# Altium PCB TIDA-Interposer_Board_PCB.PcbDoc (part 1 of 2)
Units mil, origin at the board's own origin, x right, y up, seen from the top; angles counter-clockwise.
Board outline 4000 x 3600 mil, 4 copper layers (Top Layer, GND, PWR, Bottom Layer), stack 5.48 mil thick; 55 components, 24 nets, 133 pads, 140 vias.
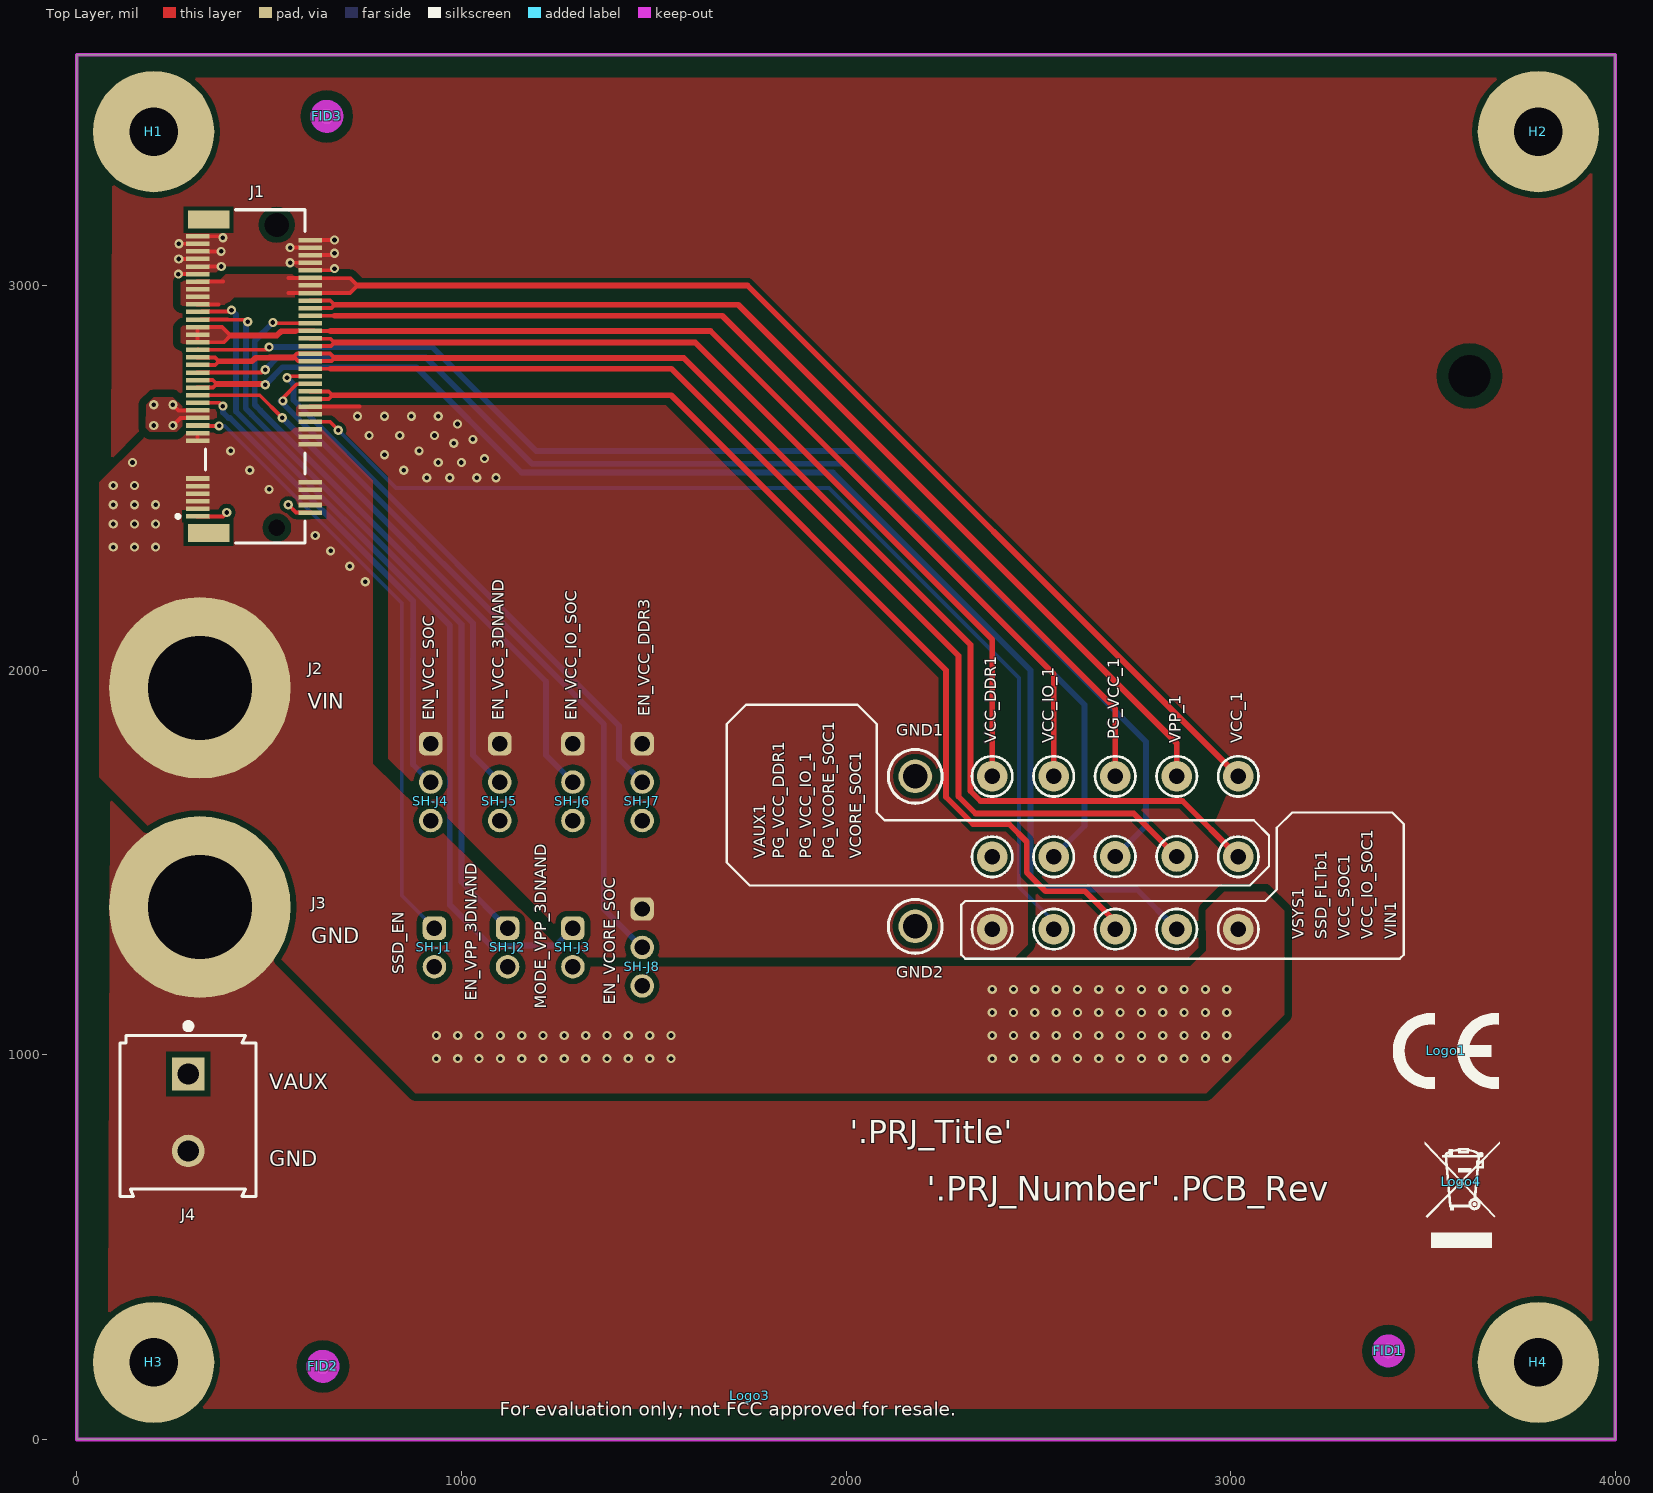
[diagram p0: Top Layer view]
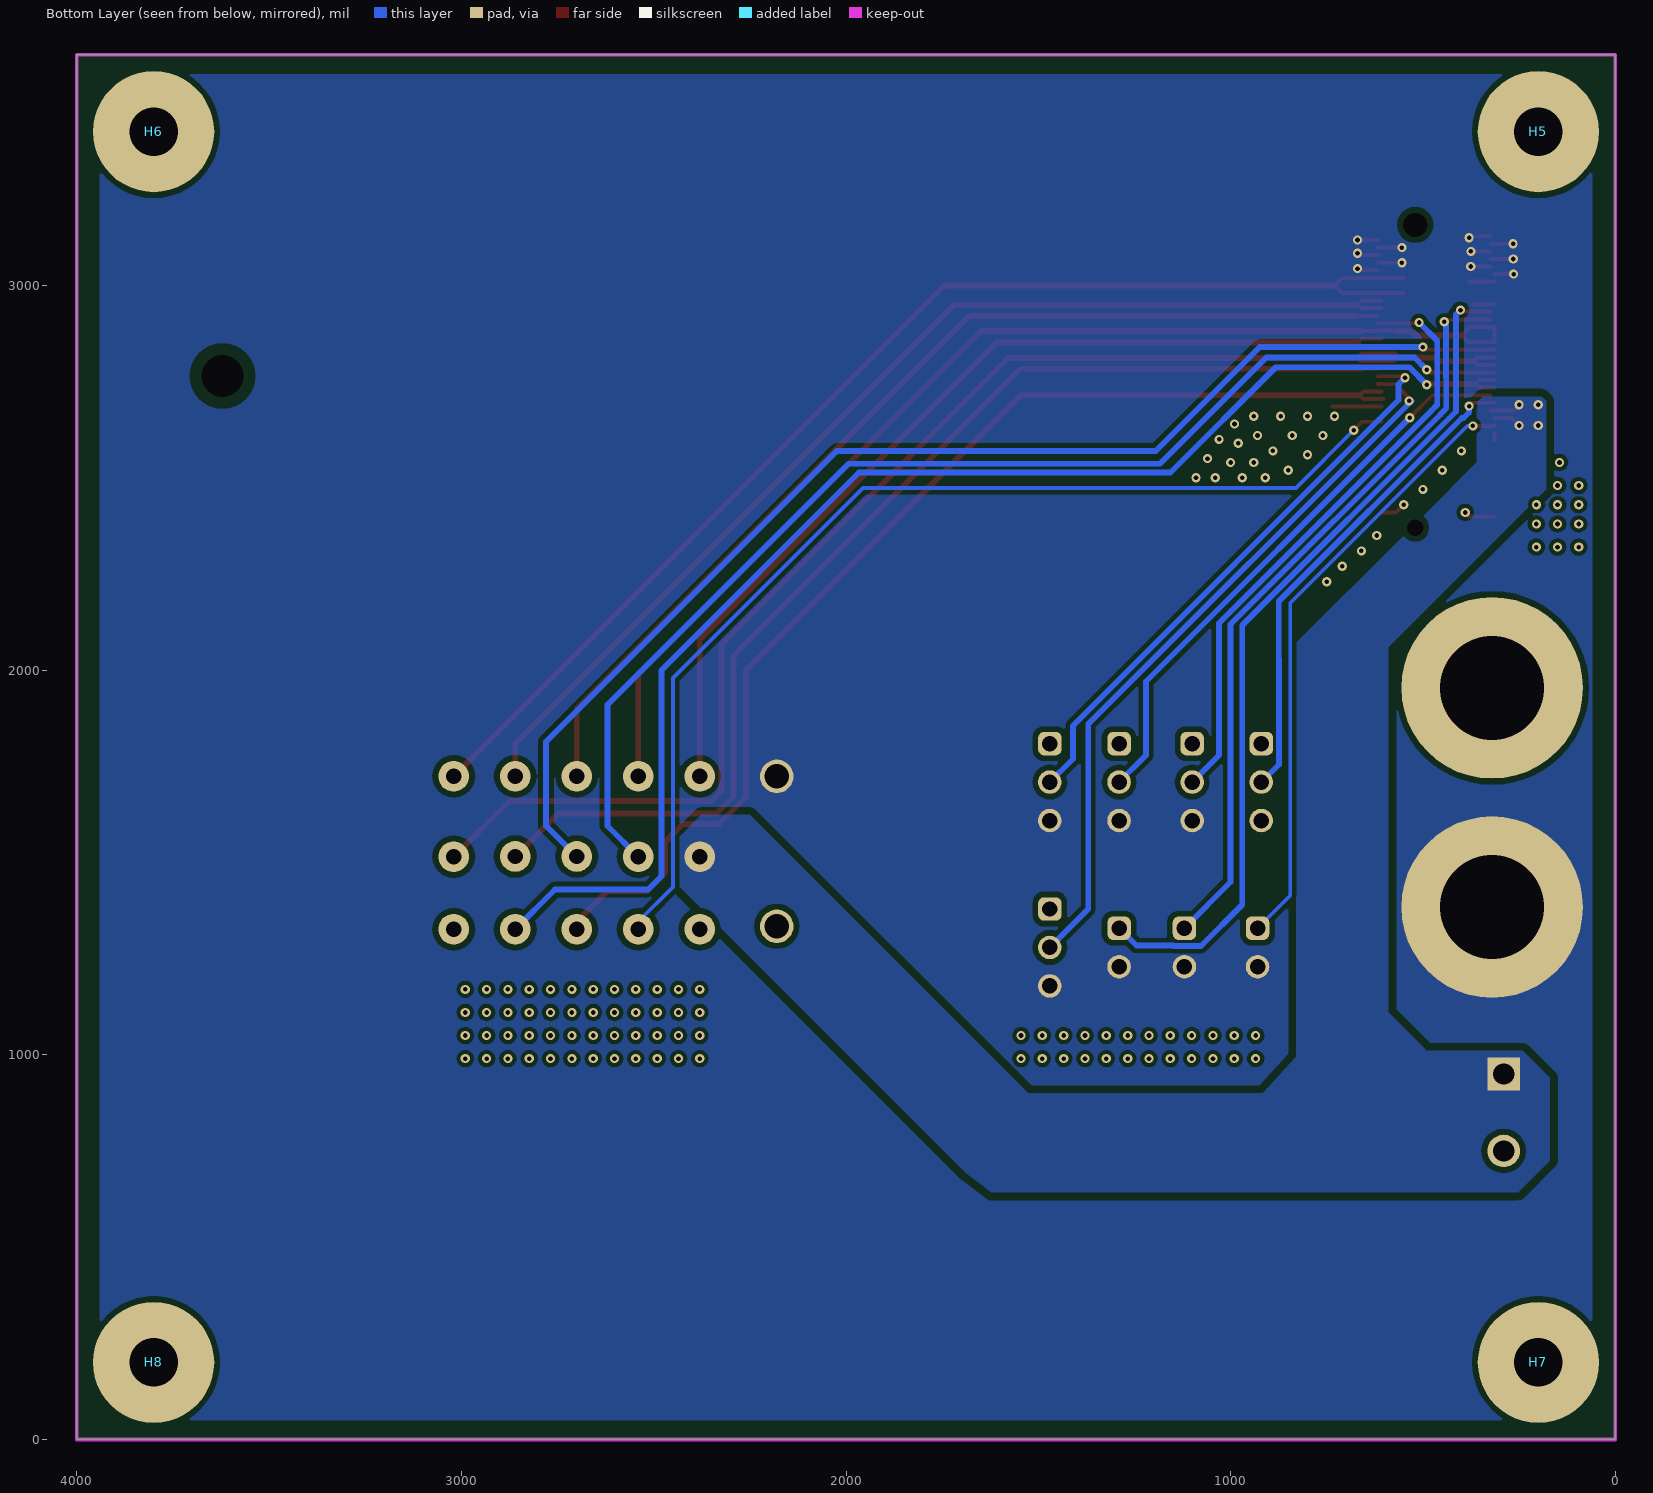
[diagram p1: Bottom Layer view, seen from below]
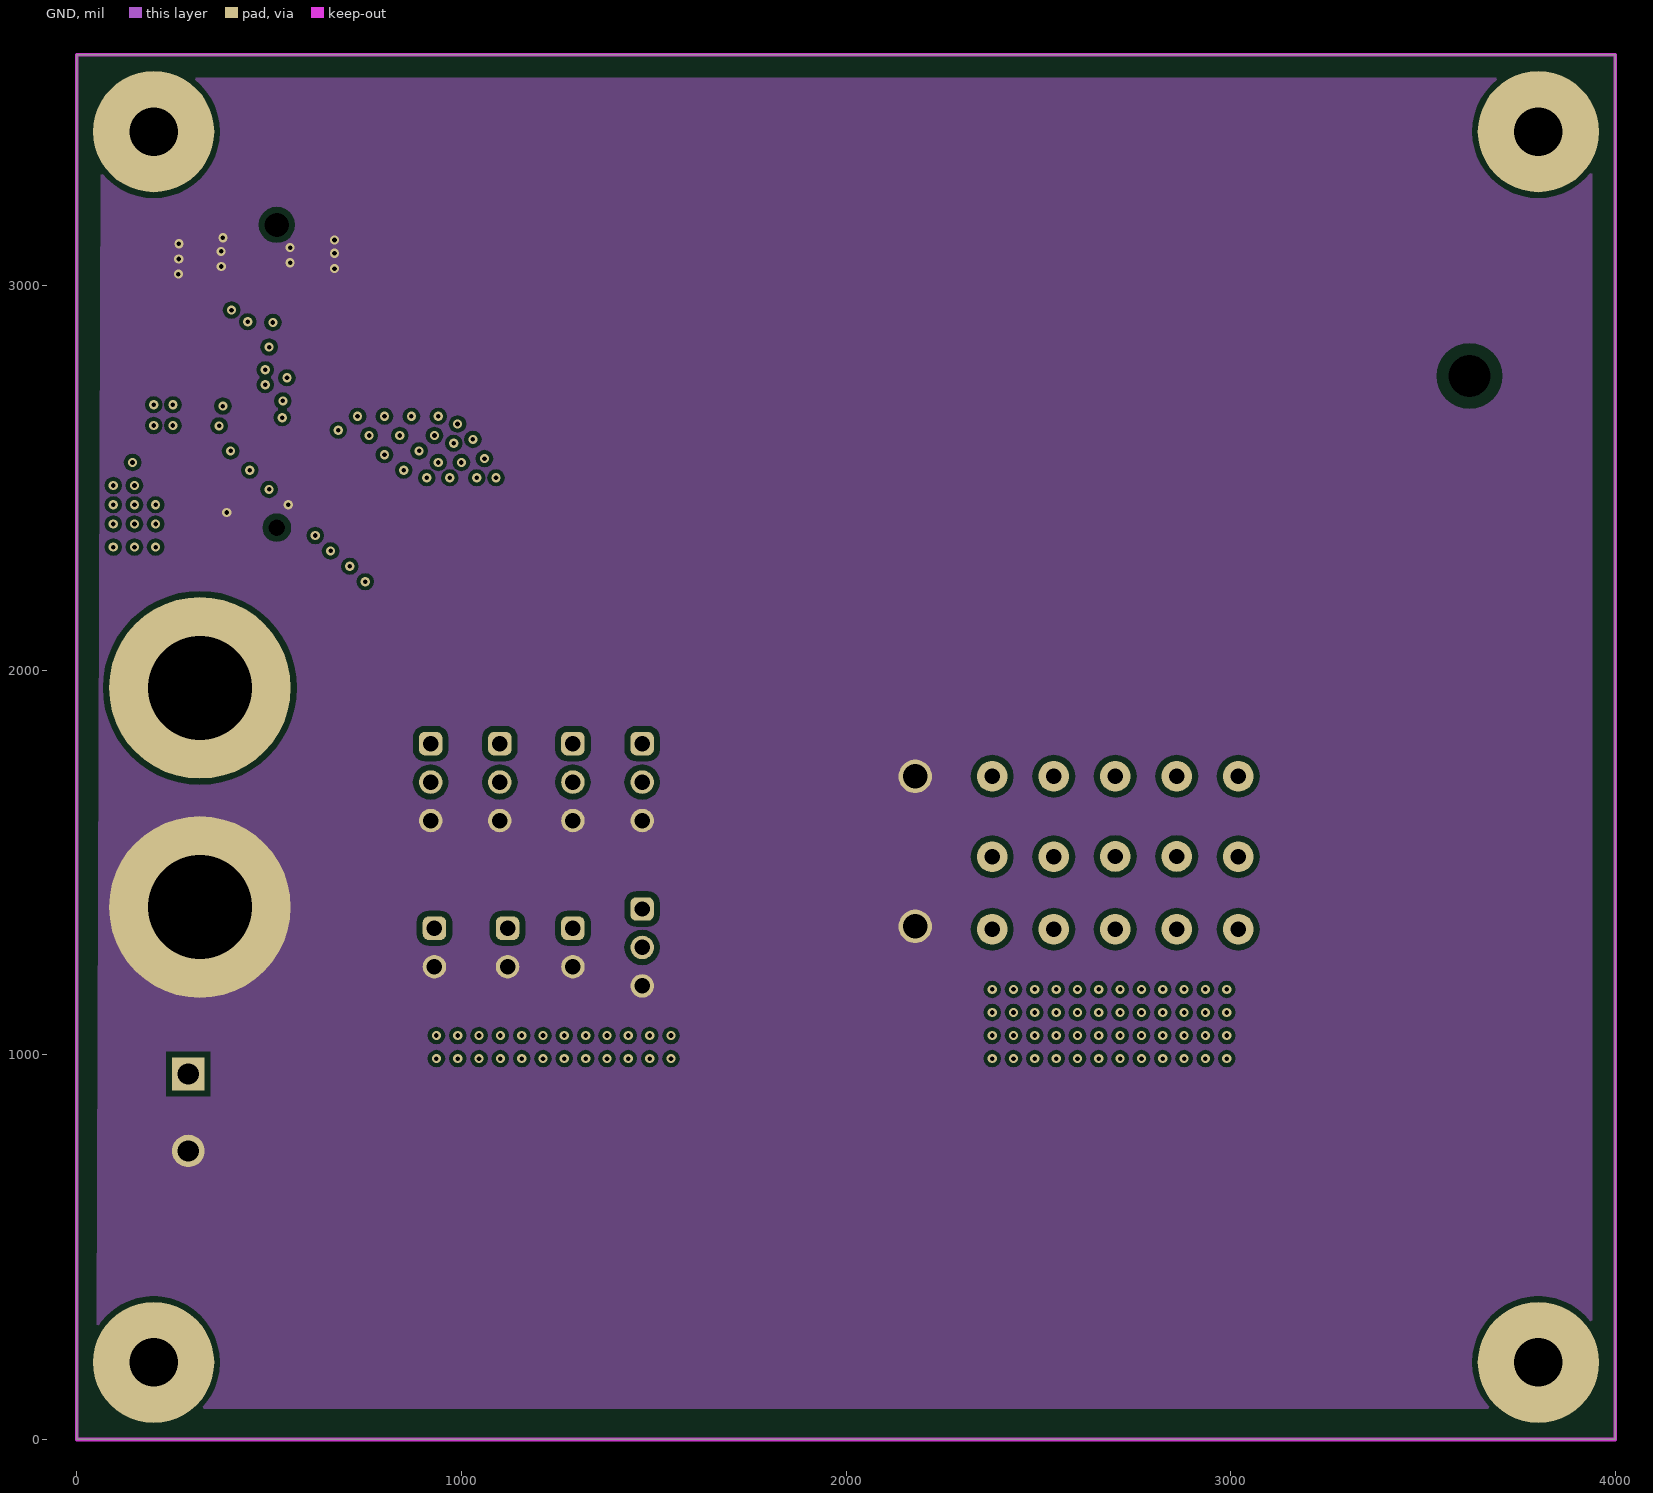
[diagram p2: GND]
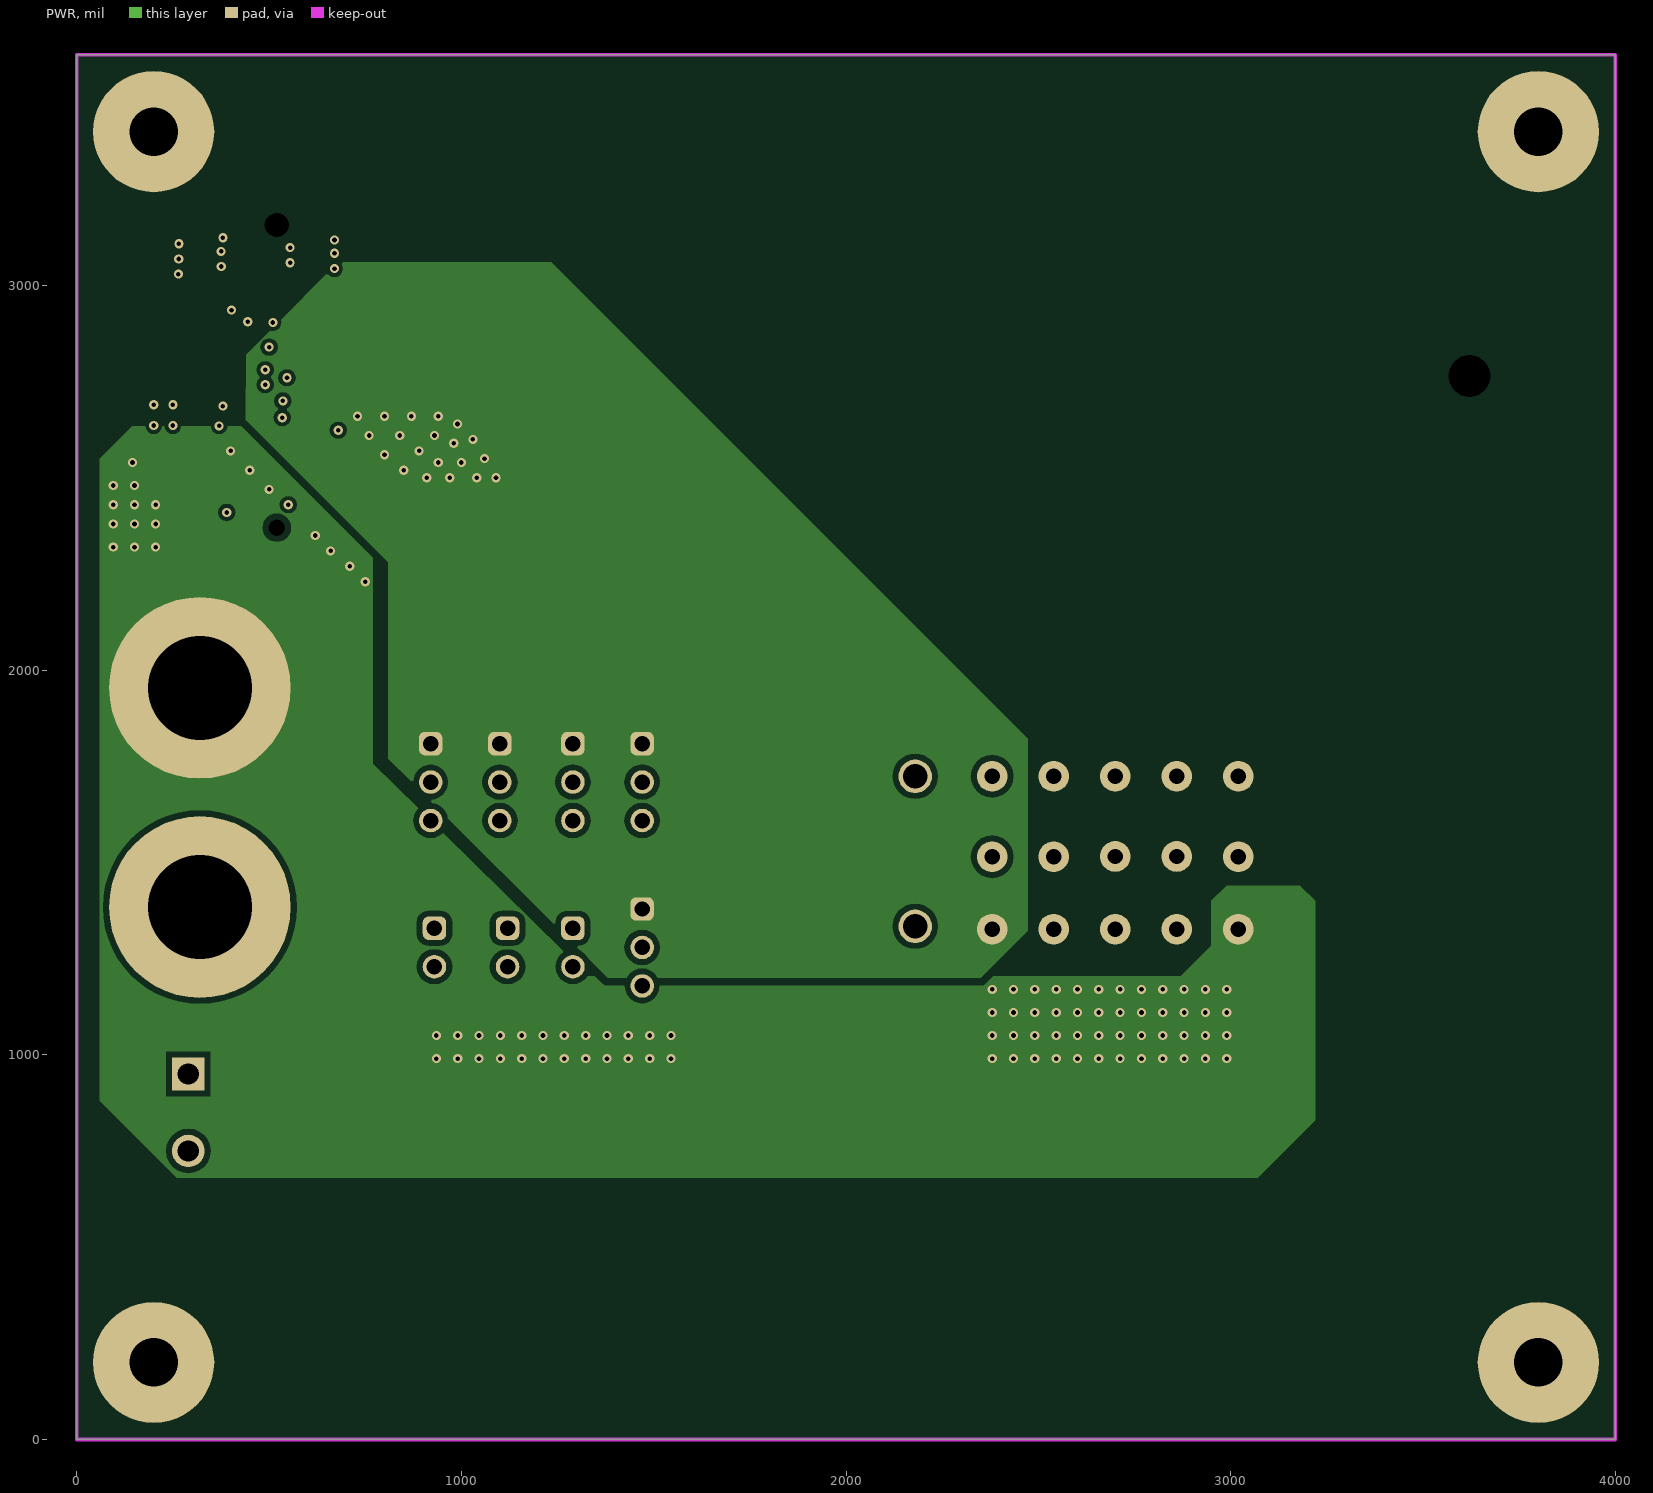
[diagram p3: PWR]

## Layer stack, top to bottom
Top Solder: solder mask 0.8, Solder Resist, Dk 0
Top Layer: signal copper 1.37
GND: signal copper 1.37
PWR: signal copper 1.37
Bottom Layer: signal copper 1.37
Bottom Solder: solder mask 0.8, Solder Resist, Dk 0

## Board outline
0,0 4000,0 4000,3600 0,3600

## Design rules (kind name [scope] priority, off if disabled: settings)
AcuteAngle [All] p1: minimum=4.50000000000000E+0001 checktracksonly=FALSE
AssemblyTestPointUsage [All] p1: valid=2
BoardOutlineClearance BoardOutlineClearance_MountingHoles [OnCopper and InComponentClass('Mounting Holes')] p1: gap=40 ignorepadtopadclearanceinfootprint=FALSE
BoardOutlineClearance BoardOutlineClearance_Poly [OnCopper and IsPoly] p2: gap=25 ignorepadtopadclearanceinfootprint=FALSE
BoardOutlineClearance [OnCopper and Not InComponentClass('Logo') and not InComponentClass('FiducialMark') and not InRegion(1000,500,4000,800) and not InPoly] p3: gap=75 ignorepadtopadclearanceinfootprint=FALSE
Clearance Clearance_MH100 [InPadClass('MH100')] p1: gap=30 ignorepadtopadclearanceinfootprint=FALSE
Clearance Clearance_Poly [InPolygon] p2: gap=25 ignorepadtopadclearanceinfootprint=FALSE except(0: Arc-Hole Track-Hole SMDPad-Hole THPad-Hole Via-Hole Fill-Hole Poly-Hole Region-Hole Text-Hole; 10: SMDPad-Poly Via-Poly; 12: Track-Poly; 15: THPad-Poly; 20: Poly-Poly)
Clearance Clearance_Keepouts [((IsTrack Or IsArc) And Not InPoly) And IsFree and IsKeepOut vs ((IsTrack Or IsArc) And Not InPoly) And IsFree and IsKeepOut] p3: gap=0 ignorepadtopadclearanceinfootprint=FALSE
Clearance [All] p4: gap=7.87 ignorepadtopadclearanceinfootprint=FALSE
Clearance Clearance_FiducialMark [IsKeepOut and InComponentClass('FID') vs IsPad and InComponentClass('FiducialMark')] p5: gap=0 ignorepadtopadclearanceinfootprint=FALSE
ComponentClearance ComponentClearance_MountingHoles_FiducialMarks [InComponentClass('Mounting Holes') vs InComponentClass('FiducialMark')] p1: gap=50 collisioncheckmode=3 verticalgap=10 showdistances=FALSE
ComponentClearance ComponentClearance_Shunt [InComponentClass('Header') vs InComponentClass('Shunt')] p2: gap=0 collisioncheckmode=3 verticalgap=0 showdistances=FALSE
ComponentClearance ComponentClearance_Logo [InComponentClass('Logo')] p3: gap=50 collisioncheckmode=3 verticalgap=10 showdistances=FALSE
ComponentClearance ComponentClearance_ScrewToNut [(HasFootprint('NY PMS 440 0025 PH')) vs (HasFootprint('Keystone_1902C'))] p4: gap=5 collisioncheckmode=3 verticalgap=10 showdistances=FALSE
ComponentClearance ComponentClearance_MountingHoles [InComponentClass('Mounting Holes')] p5: gap=100 collisioncheckmode=3 verticalgap=100000 showdistances=FALSE
ComponentClearance ComponentClearance_SmallPassives [HasFootprint('0201*') or HasFootprint('0402*') or HasFootprint('0508') or HasFootprint('0603*') or HasFootprint('0612') or HasFootprint('0805*') or HasFootprint('0815*') or HasFootprint('0830*') or HasFootprint('1206*') or HasFootprint('1210*') or HasFootprint('1808*') or HasFootprint('1812*') or HasFootprint('1825*') or HasFootprint('2010*') or HasFootprint('2220*') or HasFootprint('2225*') or HasFootprint('2512*') or HasFootprint('2728*') or HasFootprint('3518*') vs HasFootprint('0201*') or HasFootprint('0402*') or HasFootprint('0508') or HasFootprint('0603*') or HasFootprint('0612') or HasFootprint('0805*') or HasFootprint('0815*') or HasFootprint('0830*') or HasFootprint('1206*') or HasFootprint('1210*') or HasFootprint('1808*') or HasFootprint('1812*') or HasFootprint('1825*') or HasFootprint('2010*') or HasFootprint('2220*') or HasFootprint('2225*') or HasFootprint('2512*') or HasFootprint('2728*') or HasFootprint('3518*')] p6: gap=14.96 collisioncheckmode=3 verticalgap=10 showdistances=FALSE
ComponentClearance ComponentClearance_THtoSMT [IsThruComponent vs IsSMTComponent] p7: gap=40 collisioncheckmode=3 verticalgap=30 showdistances=FALSE
ComponentClearance ComponentClearance_THtoTH [IsThruComponent vs IsThruComponent] p8: gap=30 collisioncheckmode=3 verticalgap=30 showdistances=FALSE
ComponentClearance [All] p9: gap=30 collisioncheckmode=3 verticalgap=10 showdistances=FALSE
DiffPairsRouting [All] p1: maxlimit=100 minlimit=10 mostfreqgap=10 toplayer_minwidth=15 toplayer_maxwidth=15 toplayer_prefwidth=15 midlayer1_minwidth=15 midlayer1_maxwidth=15 midlayer1_prefwidth=15 midlayer2_minwidth=15 midlayer2_maxwidth=15 midlayer2_prefwidth=15 bottomlayer_minwidth=15 bottomlayer_maxwidth=15 bottomlayer_prefwidth=15 maxuncoupledlength=1000
FabricationTestPointUsage TestPointUsage [All] p1: valid=2 allowmultiple=FALSE
FabricationTestpoint Testpoint [All] p1: side=3 testpointundercomponent=TRUE minsize=40 maxsize=100 preferedsize=60 minholesize=0 maxholesize=40 preferedholesize=32 testpointgrid=1 allowsidetop=TRUE allowsidebottom=TRUE usegrid=TRUE gridtolerance=0.01
FanoutControl Fanout_LCC [IsLCC] p1: bgadir=Out bgaviamode=Centered fanoutstyle=Auto fanoutdirection=Alternating viagrid=1 // Fanout_LCC (Default Rule)
FanoutControl Fanout_BGA [IsBGA] p2: bgadir=Out bgaviamode=Centered fanoutstyle=Auto fanoutdirection=Alternating viagrid=1 // Fanout_BGA (Default Rule)
FanoutControl Fanout_Default [All] p4: bgadir=Out bgaviamode=Centered fanoutstyle=Auto fanoutdirection=Alternating viagrid=1 // Fanout_Default (Default Rule)
FanoutControl Fanout_Small [(CompPinCount < 5)] p5: bgadir=Out bgaviamode=Centered fanoutstyle=Auto fanoutdirection=OutThenIn viagrid=1 // Fanout_Small (Default Rule)
HoleSize [All] p1: absolutevalues=TRUE maxlimit=270 minlimit=7.87 maxpercent=80.000 minpercent=20.000
MinimumAnnularRing MinimumAnnularRing_ThermalPadVias [IsVia and InAnyComponent] p1: minimumring=5.91
MinimumAnnularRing [All] p2: minimumring=7.87
MinimumSolderMaskSliver MinimumSolderMaskSliver_Logo [InComponentClass('Logo') vs InComponentClass('Logo')] p1: minsoldermaskwidth=0.7
MinimumSolderMaskSliver [All] p2: minsoldermaskwidth=3.94
PlaneConnect [All] p1: planeconnectstyle=Relief reliefexpansion=10 reliefentries=4 reliefconductorwidth=10 reliefairgap=10
PolygonConnect [All] p1: connectstyle=Direct reliefconductorwidth=10 reliefentries=4 polygonreliefangle="90 Angle" airgapwidth=10
RoutingVias ThermalPadVias [IsVia and InAnyComponent] p1: holewidth=7.87 width=19.68 viastyle="Through Hole" minholewidth=7.87 minwidth=19.68 maxholewidth=12.99 maxwidth=23.62
RoutingVias [All] p2: holewidth=12 width=24 viastyle="Through Hole" minholewidth=12 minwidth=24 maxholewidth=12 maxwidth=24
SilkToBoardRegionClearance [Not ((IsComment or IsDesignator) And (Hide <> 'False')) and not InRegion(1000,500,4000,800)] p1:
SilkToSilkClearance SilkToSilkClearance_Pb-FreeLogo [(HasFootprint('Pb-Free_Overlay_Medium') OR HasFootprint('Pb-Free_Overlay_Small')) vs (HasFootprint('Pb-Free_Overlay_Medium') OR HasFootprint('Pb-Free_Overlay_Small'))] p1: silktosilkclearance=0
SilkToSilkClearance [All] p2: silktosilkclearance=4
SilkToSolderMaskClearance SilkToComponentPadClearance [(IsPad or IsFill or IsRegion) and InAnycomponent] p1: minsilkscreentomaskgap=5 clearancetoexposedcopper=TRUE
SilkToSolderMaskClearance "Silk to Solder Mask Opening" [All] p2: minsilkscreentomaskgap=4 clearancetoexposedcopper=FALSE
SolderMaskExpansion [All] p1: expansion=1.97
Width [All] p1: maxlimit=100 minlimit=6 preferedwidth=10 checkconnectedcopper=TRUE
15 further rules are at their usual default settings.

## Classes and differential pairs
component class FID: FID1 FID2 FID3
pad class MH100: Free-MH100
component class Shunt: SH-J1 SH-J2 SH-J3 SH-J4 SH-J5 SH-J6 SH-J7 SH-J8 SH-J?
component class Interposer_Board: EN_VCC_3DNAND EN_VCC_DDR3 EN_VCC_IO_SOC EN_VCC_SOC EN_VCORE_SOC EN_VPP_3DNAND GND1 GND2 J1 J2 J3 J4 J12 MODE_VPP_3DNAND PG_VCC_1 PG_VCC_DDR1 PG_VCC_IO_1 PG_VCORE_SOC1 SSD_EN SSD_FLTb1 T1 VAUX1 VCC_1 VCC_DDR1 VCC_IO_1 VCC_IO_SOC1 VCC_SOC1 VCORE_SOC1 VIN1 VPP_1 VSYS1
component class "Mounting Holes": H1 H2 H3 H4
component class EVM_Hardware: FID1 FID2 FID3 H1 H2 H3 H4 H5 H6 H7 H8 Logo1 Logo3 Logo4 SH-J1 SH-J2 SH-J3 SH-J4 SH-J5 SH-J6 SH-J7 SH-J8 SH-J? ZZ1 ZZ2 ZZ3 ZZ4
component class FiducialMark: FID1 FID2 FID3
component class AssemblyNote: ZZ1 ZZ2 ZZ3 ZZ4
component class Header: EN_VCC_3DNAND EN_VCC_DDR3 EN_VCC_IO_SOC EN_VCC_SOC EN_VCORE_SOC EN_VPP_3DNAND MODE_VPP_3DNAND SSD_EN

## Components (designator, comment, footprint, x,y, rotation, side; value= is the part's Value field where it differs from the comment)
EN_VCC_3DNAND "" Samtec_TSW-103-07-T-S 1100,1709 r270 top
EN_VCC_DDR3 "" Samtec_TSW-103-07-T-S 1470,1709 r270 top
EN_VCC_IO_SOC "" Samtec_TSW-103-07-T-S 1290,1709 r270 top
EN_VCC_SOC "" Samtec_TSW-103-07-T-S 920,1709 r270 top
EN_VCORE_SOC "" Samtec_TSW-103-07-T-S 1470,1279 r270 top
EN_VPP_3DNAND "" Samtec_TSW-102-07-T-S 1120,1279 r270 top
FID1 "Fiducial" Fiducial10-20 3410,230 r0 top
FID2 "Fiducial" Fiducial10-20 640,190 r0 top
FID3 "Fiducial" Fiducial10-20 650,3440 r0 top
GND1 "" Keystone5006 2180,1724 r270 top
GND2 "" Keystone5006 2180,1334 r0 top
H1 "NY PMS 440 0025 PH" "NY PMS 440 0025 PH" 200,3400 r0 top locked
H2 "NY PMS 440 0025 PH" "NY PMS 440 0025 PH" 3800,3400 r0 top locked
H3 "NY PMS 440 0025 PH" "NY PMS 440 0025 PH" 200,200 r0 top locked
H4 "NY PMS 440 0025 PH" "NY PMS 440 0025 PH" 3800,200 r0 top locked
H5 "1902C" Keystone_1902C 200,3400 r180 bottom locked
H6 "1902C" Keystone_1902C 3800,3400 r180 bottom locked
H7 "1902C" Keystone_1902C 200,200 r180 bottom locked
H8 "1902C" Keystone_1902C 3800,200 r180 bottom locked
J1 "SM3ZS067U310ABR1200" JAE_SM3ZS067U310ABR1200 520,2764 r90 top locked
J2 "SPC15363" Tenma_SPC15363 320,1954 r0 top
J3 "SPC15354" Tenma_SPC15354 320,1384 r90 top
J4 "VAUX" TEC_282841-2 290,850 r270 top
Logo1 "CE Mark" CE_Mark_5mm 3560,1010 r0 top
Logo3 "FCC disclaimer" FCC_disclaimer 1750,114 r0 top
Logo4 "WEEE logo" WEEE_Minimum 3600,670 r0 top
MODE_VPP_3DNAND "" Samtec_TSW-102-07-T-S 1290,1279 r270 top
PG_VCC_1 "" Keystone5002 2700,1724 r0 top
PG_VCC_DDR1 "" Keystone5002 2540,1514.77 r0 top
PG_VCC_IO_1 "" Keystone5002 2700,1515.54 r0 top
PG_VCORE_SOC1 "" Keystone5002 2860,1515.54 r0 top
SH-J1 "969102-0000-DA" SNT-100-BK-G 930,1279 r90 top value=1x2
SH-J2 "969102-0000-DA" SNT-100-BK-G 1120,1279 r90 top value=1x2
SH-J3 "969102-0000-DA" SNT-100-BK-G 1290,1279 r90 top value=1x2
SH-J4 "969102-0000-DA" SNT-100-BK-G 920,1659 r90 top value=1x2
SH-J5 "969102-0000-DA" SNT-100-BK-G 1100,1659 r90 top value=1x2
SH-J6 "969102-0000-DA" SNT-100-BK-G 1290,1659 r90 top value=1x2
SH-J7 "969102-0000-DA" SNT-100-BK-G 1470,1659 r90 top value=1x2
SH-J8 "969102-0000-DA" SNT-100-BK-G 1470,1229 r90 top value=1x2
SSD_EN "" Samtec_TSW-102-07-T-S 930,1279 r270 top
SSD_FLTb1 "" Keystone5002 2540,1326.54 r0 top
VAUX1 "" Keystone5000 2380,1514.77 r270 top
VCC_1 "" Keystone5000 3020,1724 r270 top
VCC_DDR1 "" Keystone5000 2380,1724 r0 top
VCC_IO_1 "" Keystone5000 2540,1724 r0 top
VCC_IO_SOC1 "" Keystone5000 2860,1326.54 r0 top
VCC_SOC1 "" Keystone5000 2700,1326.54 r0 top
VCORE_SOC1 "" Keystone5000 3020,1514.77 r0 top
VIN1 "" Keystone5000 3020,1326.54 r0 top
VPP_1 "" Keystone5000 2860,1724 r0 top
VSYS1 "" Keystone5000 2380,1326.54 r0 top
ZZ1 "This Assembly Note is for PCB labels only" AssemblyNoteLabel 180,4344 r0 top
ZZ2 "These assemblies are ESD sensitive, ESD precautions shall be observed." AssemblyNote 175,4233.11 r0 top
ZZ3 "These assemblies must be clean and free from flux and all contaminants. Use of no clean flux is not acceptable." AssemblyNote 175,4144.56 r0 top
ZZ4 "These assemblies must comply with workmanship standards IPC-A-610 Class 2, unless otherwise specified." AssemblyNote 175,4056 r0 top

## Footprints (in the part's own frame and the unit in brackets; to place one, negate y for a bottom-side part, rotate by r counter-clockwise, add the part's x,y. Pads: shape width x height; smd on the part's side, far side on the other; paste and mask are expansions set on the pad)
AssemblyNote [mil] "Assembly Note"
AssemblyNoteLabel [mil] "Assembly Note for PCB Labels"
CE_Mark_5mm [mil] "Minimum text height for CE Mark"
  silkscreen extent -138,-98 138,98
FCC_disclaimer [mil]
Fiducial10-20 [mm]
  round 1 smd mask+0.5: 1(0,0)
  Top Layer keep-out circle w1.178: c0,0 r0.5
JAE_SM3ZS067U310ABR1200 [mm] "Edgeboard, B Key, 0.5mm, SMD"
  rect 0.3x1.55 smd: 1(-9.25,5.225) 2(-9,-2.225) 3(-8.75,5.225) 4(-8.5,-2.225) 5(-8.25,5.225) 6(-8,-2.225) 7(-7.75,5.225) 8(-7.5,-2.225) 9(-7.25,5.225) 10(-7,-2.225) 11(-6.75,5.225) 20(-4.5,-2.225) 21(-4.25,5.225) 22(-4,-2.225) 23(-3.75,5.225) 24(-3.5,-2.225) 25(-3.25,5.225) 26(-3,-2.225) 27(-2.75,5.225) 28(-2.5,-2.225) 29(-2.25,5.225) 30(-2,-2.225) 31(-1.75,5.225) 32(-1.5,-2.225) 33(-1.25,5.225) 34(-1,-2.225) 35(-0.75,5.225) 36(-0.5,-2.225) 37(-0.25,5.225) 38(0,-2.225) 39(0.25,5.225) 40(0.5,-2.225) 41(0.75,5.225) 42(1,-2.225) 43(1.25,5.225) 44(1.5,-2.225) 45(1.75,5.225) 46(2,-2.225) 47(2.25,5.225) 48(2.5,-2.225) 49(2.75,5.225) 50(3,-2.225) 51(3.25,5.225) 52(3.5,-2.225) 53(3.75,5.225) 54(4,-2.225) 55(4.25,5.225) 56(4.5,-2.225) 57(4.75,5.225) 58(5,-2.225) 59(5.25,5.225) 60(5.5,-2.225) 61(5.75,5.225) 62(6,-2.225) 63(6.25,5.225) 64(6.5,-2.225) 65(6.75,5.225) 66(7,-2.225) 67(7.25,5.225) 68(7.5,-2.225) 69(7.75,5.225) 70(8,-2.225) 71(8.25,5.225) 72(8.5,-2.225) 73(8.75,5.225) 74(9,-2.225) 75(9.25,5.225)
  round 1 hole 1.1 unplated mask+0.127: MH1(-10,0)
  round 1 hole 1.6 unplated mask+0.127: MH2(10,0)
  rect 1.2x2.75 smd: MP1(-10.35,4.5) MP2(10.35,4.5)
  silkscreen extent -11,-1.85 11,6.63, body extent -11,-1.85 11,4.7, height 3.2
Keystone5000 [mil] "For Keystone 500x miniature loop terminals"
  round 80 hole 40: 1(0,0)
  silkscreen extent -52,-52 52,52, body extent -49,-49 49,49, height 182
Keystone5002 [mil] "For Keystone 500x miniature loop terminals"
  round 80 hole 40: 1(0,0)
  silkscreen extent -52,-52 52,52, body extent -49,-49 49,49, height 182
Keystone5006 [mil] "Keystone Compact loops"
  round 87 hole 63: 1(0,0)
  silkscreen extent -70,-70 70,70, body extent -63,-63 62,63, height 225
Keystone_1902C [mil] "Hex Standoff, 4-40 threaded, nylon"
  round 1 on Mech4: 0(0,0)
  body extent -145,-126 146,126, height 501
"NY PMS 440 0025 PH" [mm] "4-40 nylon screw and mounting hole"
  round 8 hole 3.2: 1(0,0)
  body extent -3.3,-3.3 3.3,3.3, height 2.69
Samtec_TSW-102-07-T-S [mm] "Header, 2.54 mm, 2x1, Tin, TH"
  rrect50% 1.55x1.55 hole 1.02: 1(-1.27,0)
  round 1.55 hole 1.02: 2(1.27,0)
  body extent -2.54,-1.27 2.54,1.27, height 8.38
Samtec_TSW-103-07-T-S [mm] "Header, 2.54 mm, 3x1, TH"
  rrect50% 1.55x1.55 hole 1.02: 1(-2.54,0)
  round 1.55 hole 1.02: 2(0,0) 3(2.54,0)
  body extent -3.81,-1.27 3.81,1.27, height 8.39
SNT-100-BK-G [mil] "Samtec STEP model"
  round 1 on Mech3: 0(0,0)
  body extent -100,-50 100,50, height 344
TEC_282841-2 [mm] "TE Connectivity"
  rect 2.15x2.15 hole 1.4: 1(-2.54,0)
  round 2.15 hole 1.4: 2(2.54,0)
  silkscreen extent -5.9,-4.52 5.55,4.47, body extent -5.08,-4.52 5.58,4.48, height 15.2
Tenma_SPC15354 [mm] "Insulated Banana Jack, Black"
  round 12 hole 6.858: 1(0,0)
  body extent -6.3,-6.34 6.35,6.34, height 8.8
Tenma_SPC15363 [mm] "Insulated Banana Jack, Red"
  round 12 hole 6.858: 1(0,0)
  body extent -6.3,-6.34 6.35,6.34, height 8.8
WEEE_Minimum [mil] "WEEElie bin"
  silkscreen extent -95,-172 99,104

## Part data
EN_VCC_3DNAND EN_VCC_DDR3 EN_VCC_IO_SOC EN_VCC_SOC EN_VCORE_SOC: library part CMP-0075530-2, "Header, 2.54 mm, 3x1, Tin, TH", Color=Black, Current_A=6.3A, Manufacturer=Samtec, PartNumber=TSW-103-07-T-S, Supplier Part Number 1=SAM1035-03-ND, Voltage_V=550V
EN_VPP_3DNAND MODE_VPP_3DNAND SSD_EN: library part CMP-0075508-2, "Header, 2.54 mm, 2x1, Tin, TH", Color=Black, Current_A=6.3A, Manufacturer=Samtec, PartNumber=TSW-102-07-T-S, Supplier Part Number 1=SAM1035-02-ND, Voltage_V=550V
FID1 FID2 FID3: library part CMP-0077181-1, "Fiducial mark.  There is nothing to buy or mount.", Manufacturer=N/A
GND1 GND2: library part CMP-0055143-1, "Test Point, Compact, Black, TH", Color=Black, Manufacturer=Keystone, PartNumber=5006, Supplier Part Number 1=36-5006-ND
H1 H2 H3 H4: library part CMP-0003617-1, "Machine Screw, Round, #4-40 x 1/4, Nylon, Philips panhead", Manufacturer="B&F Fastener Supply", Supplier Part Number 1=H542-ND
H5 H6 H7 H8: library part CMP-0003610-1, "Standoff, Hex, 0.5\"L #4-40 Nylon", Manufacturer=Keystone, Supplier Part Number 1=36-1902C-ND
J1: library part CMP-0075070-1, "PCI Express M.2 connector, 0.5mm, B Key, Gold, R/A, SMD", Manufacturer="JAE Electronics", Supplier Part Number 1=670-2688-1-ND
J2: library part CMP-0055399-2, "BANANA JACK, SOLDER LUG, RED, TH", Manufacturer=Tenma, Supplier Part Number 1=79K4950
J3: library part CMP-0055398-2, "BANANA JACK, SOLDER LUG, BLACK, TH", Manufacturer=Tenma, Supplier Part Number 1=79K4944
J4: library part CMP-0054973-1, "Terminal Block, 2x1, 5.08mm, TH", Manufacturer="TE Connectivity", PartNumber=282841-2, Supplier Part Number 1=A98342-ND
Logo1: library part CMP-0074844-1
Logo3: library part CMP-0074847-1, "FCC_disclaimer"
Logo4: library part CMP-0074769-1
PG_VCC_1 PG_VCC_DDR1 PG_VCC_IO_1 PG_VCORE_SOC1 SSD_FLTb1: library part CMP-0055139-1, "Test Point, Miniature, White, TH", Color=White, Manufacturer=Keystone, PartNumber=5002, Supplier Part Number 1=36-5002-ND
SH-J1 SH-J2 SH-J3 SH-J4 SH-J5 SH-J6 SH-J7 SH-J8: library part CMP-0003614-1, "Shunt, 100mil, Gold plated, Black", Alternate Manufacturer=Samtec, Alternate PartNumber=SNT-100-BK-G, Manufacturer=3M, Supplier Part Number 1=3M9580-ND
VAUX1 VCC_1 VCC_DDR1 VCC_IO_1 VCC_IO_SOC1 VCC_SOC1 VCORE_SOC1 VIN1 VPP_1 VSYS1: library part CMP-0055137-1, "Test Point, Miniature, Red, TH", Color=Red, Manufacturer=Keystone, PartNumber=5000, Supplier Part Number 1=36-5000-ND
ZZ1: library part CMP-0003616-3
ZZ2: library part CMP-0077236-1
ZZ3: library part CMP-0077237-1
ZZ4: library part CMP-0077238-1

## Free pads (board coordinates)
  round 0 hole 110 unplated mask+5: MH100(3621.25,2764.63)

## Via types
v1: diameter 24, hole 12, Top Layer to Bottom Layer, 140 vias

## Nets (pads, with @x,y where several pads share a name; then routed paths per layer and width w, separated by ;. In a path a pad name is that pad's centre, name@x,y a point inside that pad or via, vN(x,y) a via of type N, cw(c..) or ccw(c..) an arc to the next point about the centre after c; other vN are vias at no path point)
EN_VCC_3DNAND: EN_VCC_3DNAND.2 J1.52 | length 1587.5
  Top Layer w10: v1(510,2904) 514.09,2904 516.3,2901.8 J1.52@607.6,2901.8 J1.52@617.6,2901.8
  Bottom Layer w15: v1(510,2904) 462.63,2856.63 462.63,2769.72 462.87,2769.47 462.87,2753.84 462.5,2753.46 462.5,2689.79 477.39,2674.9 477.39,2674.39 1030,2121.78 1030,1779 EN_VCC_3DNAND.2@1100,1709
EN_VCC_DDR3: EN_VCC_DDR3.2 J1.38 | length 1506.3
  Top Layer w10: v1(546.46,2760) 550.46,2764 J1.38@607.6,2764 J1.38@617.6,2764
  Bottom Layer w15: v1(546.46,2760) 563.24,2743.23 563.24,2702.05 1410,1855.29 1410,1769 EN_VCC_DDR3.2@1470,1709
EN_VCC_IO_SOC: EN_VCC_IO_SOC.2 J1.33 | length 1494.5
  Top Layer w10: J1.33@324.29,2714.79 475.71,2714.79 v1(534.01,2656.49)
  Bottom Layer w15: v1(534.01,2656.49) 1220,1970.5 1220,1779 EN_VCC_IO_SOC.2@1290,1709
EN_VCC_SOC: EN_VCC_SOC.2 J1.31 | length 1273.6
  Top Layer w10: J1.31@314.29,2695.1 371.49,2695.1 v1(380,2686.59)
  Bottom Layer w15: v1(380,2686.59) 380,2670 394.48,2655.52 398.47,2655.52 875,2178.99 875,2030 874.11,2029.11 874.11,1754.89 EN_VCC_SOC.2@920,1709
EN_VCORE_SOC: EN_VCORE_SOC.2 J1.36 | length 1921.2
  Top Layer w10: v1(535.86,2700) 535.86,2707.52 571.75,2743.41 607.6,2743.41 J1.36@607.6,2744.31 J1.36@617.6,2744.31
  Bottom Layer w15: v1(535.86,2700) 530,2700 1370,1860 1370,1379 EN_VCORE_SOC.2@1470,1279
EN_VPP_3DNAND: EN_VPP_3DNAND.1 J1.53 | length 1982.9
  Top Layer w10: J1.53@324.29,2911.64 391.65,2911.64 392.09,2911.2 438.8,2911.2 v1(444.28,2905.72)
  Bottom Layer w15: v1(444.28,2905.72) 439.75,2901.2 439.75,2763.06 439.63,2762.94 439.63,2680.32 454.52,2665.43 454.52,2664.92 1000,2119.43 1000,1449 EN_VPP_3DNAND.1@1120,1329
GND: EN_VCC_3DNAND.3 EN_VCC_DDR3.3 EN_VCC_IO_SOC.3 EN_VCC_SOC.3 EN_VCORE_SOC.3 EN_VPP_3DNAND.2 GND1.1 GND2.1 J1.1 J1.2 J1.65 J1.66 J1.67 J1.68 J1.69 J1.70 J1.71 J1.72 J1.73 J1.74 J1.75 J3.1 J4.2 MODE_VPP_3DNAND.2 SSD_EN.2 | length 760.5
  Top Layer w10: v1(264.25,3029.75) J1.65@314.29,3029.75 ; v1(264.88,3069.12) J1.69@314.29,3069.12 J1.69@324.29,3069.12 ; v1(265.51,3108.49) J1.73@314.29,3108.49 J1.73@324.29,3108.49 ; J1.1@314.29,2399.83 379.83,2399.83 v1(390,2410) ; J1.67@324.29,3049.43 v1(375.43,3049.43) ; J1.71@324.29,3088.8 v1(375.2,3088.8) ; J1.75@324.29,3128.17 375.83,3128.17 v1(380,3124) ; v1(550,2430) 570.33,2409.67 J1.2@607.6,2409.67 ; v1(554.72,3059.28) J1.68@607.6,3059.28 J1.68@617.6,3059.28 ; v1(554.72,3098.65) J1.72@607.6,3098.65 J1.72@617.6,3098.65 ; J1.66@617.6,3039.59 665.59,3039.59 v1(670,3044) ; J1.70@617.6,3078.96 664.96,3078.96 v1(670,3084) ; J1.74@617.6,3118.33 v1(670,3118.33)
MODE_VPP_3DNAND: J1.55 MODE_VPP_3DNAND.1 | length 2246.5
  Top Layer w10: J1.55@324.29,2931.32 325.2,2932.23 401.57,2932.23 402.45,2933.11 v1(402.45,2936.2)
  Bottom Layer w15: v1(402.45,2936.2) 414.25,2924.39 414.25,2672.36 970,2116.61 970,1390 1076.89,1283.11 1147.94,1283.11 1148.83,1284 1245,1284 MODE_VPP_3DNAND.1@1290,1329
PG_VCC_3DNAND: J1.54 PG_VCC_1.1 | length 2686.2
  Top Layer w10: J1.54@617.6,2921.48 670,2921.48 ; PG_VCC_1.1@2710,1724 PG_VCC_1.1@2710,1728.72
  Top Layer w15: 670,2921.48 1678.52,2921.48 2700,1900 PG_VCC_1.1@2700,1724
PG_VCC_DDR3: J1.39 PG_VCC_DDR1.1 | length 3124
  Top Layer w10: J1.39@314.29,2773.84 314.55,2774.1 479.9,2774.1 486.86,2781.06 v1(490,2781.06)
  Bottom Layer w15: v1(490,2781.06) 521.56,2812.63 907.37,2812.63 1183.5,2536.5 1993.5,2536.5 2620,1910 2620,1594.77 PG_VCC_DDR1.1@2540,1514.77
PG_VCC_IO_3DNAND: J1.45 PG_VCC_IO_1.1 | length 3228.1
  Top Layer w10: J1.45@315.2,2833.8 J1.45@314.29,2832.9 492.9,2832.9 v1(500,2840)
  Bottom Layer w10: PG_VCC_IO_1.1@2698.46,1515.54 PG_VCC_IO_1.1@2700,1515.54
  Bottom Layer w15: v1(500,2840) 924.37,2840 1194.37,2570 2024,2570 2780,1814 2780,1595.54 PG_VCC_IO_1.1@2700,1515.54
PG_VCORE_SOC: J1.40 PG_VCORE_SOC1.1 | length 2996.2
  Top Layer w10: J1.40@617.6,2783.69 660,2783.69 ; PG_VCORE_SOC1.1@2870,1525.54 PG_VCORE_SOC1.1@2880,1515.54
  Top Layer w15: 660,2783.69 1546.31,2783.69 2292.5,2037.5 2292.5,1671.5 2336.87,1627.13 2748.42,1627.13 PG_VCORE_SOC1.1@2860,1515.54
SSD_EN: J1.25 SSD_EN.1 | length 1604.2
  Top Layer w10: J1.25@314.29,2636.05 315.2,2635.14 J1.25@325.2,2635.14 ; J1.25@324.29,2636.05 J1.25@325.2,2635.14 ; v1(370,2635.14) J1.25@325.2,2635.14
  Bottom Layer w10: v1(370,2635.14) 384.86,2635.14 845,2175 845,1414 SSD_EN.1@930,1329
SSD_FLTb: J1.26 SSD_FLTb1.1 | length 2809
  Top Layer w10: J1.26@607.6,2645.89 658.11,2645.89 v1(680,2624)
  Bottom Layer w10: v1(680,2624) 830,2474 1956,2474 2450,1980 2450,1436.54 2540,1346.54 SSD_FLTb1.1@2540,1326.54
VAUX: J1.27 J1.29 J4.1 VAUX1.1 | length 152.8
  Top Layer w10: v1(250,2636) 269.73,2655.73 J1.27@314.29,2655.73 ; v1(250,2690) 264.58,2675.42 J1.29@314.29,2675.42 J1.29@324.29,2675.42
  other v1: 200,2636 200,2690
VCC_3DNAND: J1.57 J1.59 J1.60 J1.61 J1.62 J1.63 J1.64 VCC_1.1 | length 3315.1
  Top Layer w10: J1.57@314.29,2951.01 369.09,2951.01 ; J1.63@314.29,3010.06 379.94,3010.06 ; 550.09,3019.91 J1.64@607.6,3019.91 ; 550.54,2980.54 J1.60@607.6,2980.54 710.54,2980.54 730,3000 710.87,3019.13 J1.64@617.6,3019.13 ; J1.64@607.6,3019.13 J1.64@617.6,3019.13 ; J1.64@617.6,3019.91 J1.64@617.6,3019.13
  Top Layer w15: 730,3000 1744,3000 VCC_1.1@3020,1724
VCC_DDR3: J1.46 J1.48 VCC_DDR1.1 | length 2519
  Top Layer w10: J1.46@607.6,2842.74 661,2842.74 670,2851.74 660,2861.74 J1.48@617.6,2861.74 ; J1.48@607.6,2861.74 J1.48@617.6,2861.74 ; J1.48@617.6,2862.43 J1.48@617.6,2861.74
  Top Layer w15: 670,2851.74 1608.26,2851.74 2380,2080 VCC_DDR1.1@2380,1724
VCC_IO_3DNAND: J1.47 J1.49 J1.50 J1.51 VCC_IO_1.1 | length 3007.7
  Top Layer w10: 568.44,2883.02 616.69,2883.02 617.6,2882.11 660,2882.11 ; J1.47@314.29,2852.58 J1.49@314.29,2872.27 J1.51@314.29,2891.95 378.05,2891.95 400,2870 382.58,2852.58 J1.47@314.29,2852.58
  Top Layer w15: 400,2870 520,2870 531.42,2881.42 568.44,2881.42 ; 660,2882.11 1647.89,2882.11 2540,1990 VCC_IO_1.1@2540,1724
VCC_IO_SOC: J1.35 J1.37 VCC_IO_SOC1.1 | length 3556.1
  Top Layer w10: J1.35@314.29,2734.47 354.47,2734.47 363.88,2743.88 353.61,2754.16 J1.37@314.29,2754.16
  Top Layer w15: 363.88,2743.88 488.12,2743.88 v1(489.87,2742.13)
  Bottom Layer w15: v1(489.87,2742.13) 535.12,2787.37 882.63,2787.37 1156.37,2513.63 1966.37,2513.63 2480,2000 2480,1464 2514,1430 2756.54,1430 VCC_IO_SOC1.1@2860,1326.54 ; VCC_IO_SOC1.1@2870,1336.54 VCC_IO_SOC1.1@2880,1326.54
VCC_SOC: J1.32 J1.34 VCC_SOC1.1 | length 2990.5
  Top Layer w10: J1.32@602.6,2705.63 607.6,2705.63 J1.32@607.6,2704.94 655.32,2704.94 665,2714.63 655,2724.63 J1.34@607.6,2724.63
  Top Layer w15: 665,2714.63 1545.37,2714.63 2260,2000 2260,1670 2330,1600 2424,1600 2470,1554 2470,1474 2518.73,1425.27 2621.27,1425.27 2700,1346.54 VCC_SOC1.1@2700,1326.54
VCORE_SOC: J1.41 J1.42 J1.43 J1.44 VCORE_SOC1.1 | length 3658.9
  Top Layer w10: J1.41@314.29,2793.53 359.96,2793.53 369.65,2803.21 359.65,2813.21 J1.43@314.29,2813.21 ; 562.63,2812.63 573.06,2823.06 J1.44@607.6,2823.06 658.82,2823.06 670,2811.87 662.18,2804.06 575.45,2804.06 566.89,2812.63 ; VCORE_SOC1.1@3025,1519.77 VCORE_SOC1.1@3030,1514.77
  Top Layer w15: 369.65,2803.21 455.84,2803.21 465.15,2812.52 501.34,2812.52 501.44,2812.63 562.63,2812.63 ; 670,2811.87 1578.13,2811.87 2324,2066 2324,1686 2350,1660 2874.77,1660 VCORE_SOC1.1@3020,1514.77
VIN: J1.3 J1.4 J1.5 J1.6 J1.7 J1.8 J1.9 J1.10 J1.11 J1.20 J1.21 J1.22 J1.23 J1.24 J2.1 VIN1.1 | length 19.7
  Top Layer w10: J1.21@314.29,2596.68 J1.23@314.29,2616.36
  other v1: 935,990 990.45,990 1045.91,990 1101.36,990 1156.82,990 1212.27,990 1267.73,990 1323.18,990 1378.64,990 1434.09,990 1489.55,990 1545,990 2380,990 2435.45,990 2490.91,990 2546.36,990 2601.82,990 2657.27,990 2712.73,990 2768.18,990 2823.64,990 2879.09,990 2934.55,990 2990,990 935,1050 990.45,1050 1045.91,1050 1101.36,1050 1156.82,1050 1212.27,1050 1267.73,1050 1323.18,1050 1378.64,1050 1434.09,1050 1489.55,1050 1545,1050 2380,1050 2435.45,1050 2490.91,1050 2546.36,1050 2601.82,1050 2657.27,1050 2712.73,1050 2768.18,1050 2823.64,1050 2879.09,1050 2934.55,1050 2990,1050 2380,1110 2435.45,1110 2490.91,1110 2546.36,1110 2601.82,1110 2657.27,1110 2712.73,1110 2768.18,1110 2823.64,1110 2879.09,1110 2934.55,1110 2990,1110 2380,1170 2435.45,1170 2490.91,1170 2546.36,1170 2601.82,1170 2657.27,1170 2712.73,1170 2768.18,1170 2823.64,1170 2879.09,1170 2934.55,1170 2990,1170 750,2230 710,2270 660,2310 95,2320 150,2320 205,2320 620,2350 95,2380 150,2380 205,2380 95,2430 150,2430 205,2430 500,2470 95,2480 150,2480 450,2520 145,2540 400,2570
VPP_3DNAND: J1.56 J1.58 VPP_1.1 | length 2881.6
  Top Layer w10: J1.56@607.6,2941.17 607.6,2941.85 661.85,2941.85 670,2950 659.15,2960.85 J1.58@607.6,2960.85
  Top Layer w15: 670,2950 1720,2950 2860,1810 VPP_1.1@2860,1724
